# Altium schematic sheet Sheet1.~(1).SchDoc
size A4
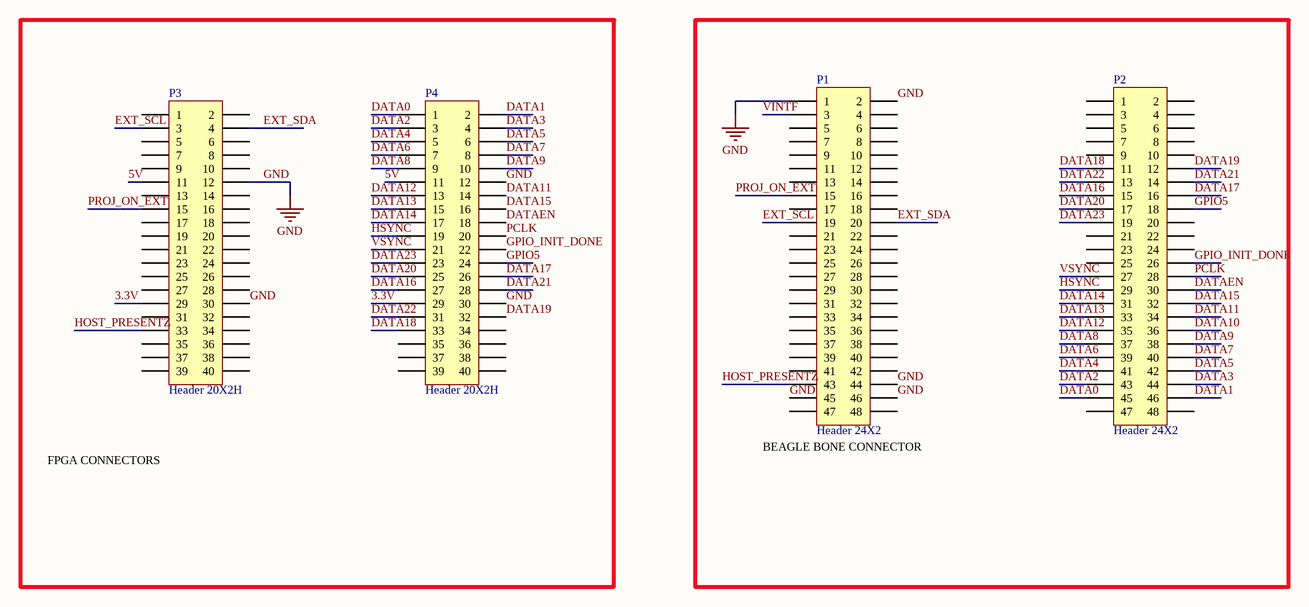
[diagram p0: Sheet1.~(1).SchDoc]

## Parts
P1  Header 24X2  [HDR2X24]
P2  Header 24X2  [HDR2X24]
P3  Header 20X2H  [HDR2X20H]
P4  Header 20X2H  [HDR2X20H]

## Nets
GND: P1.1 P1.2 P1.44 P1.45 P1.46 P3.12 P3.30 P4.12 P4.30
3.3V: P3.29 P4.29
5V: P3.11 P4.11
DATA0: P2.45 P4.1
DATA1: P2.46 P4.2
DATA2: P2.43 P4.3
DATA3: P2.44 P4.4
DATA4: P2.41 P4.5
DATA5: P2.42 P4.6
DATA6: P2.39 P4.7
DATA7: P2.40 P4.8
DATA8: P2.37 P4.9
DATA9: P2.38 P4.10
DATA10: P2.36
DATA11: P2.34 P4.14
DATA12: P2.35 P4.13
DATA13: P2.33 P4.15
DATA14: P2.31 P4.17
DATA15: P2.32 P4.16
DATA16: P2.15 P4.27
DATA17: P2.16 P4.26
DATA18: P2.11 P4.33
DATA19: P2.12 P4.32
DATA20: P2.17 P4.25
DATA21: P2.14 P4.28
DATA22: P2.13 P4.31
DATA23: P2.19 P4.23
DATAEN: P2.30 P4.18
EXT_SCL: P1.19 P3.3
EXT_SDA: P1.20 P3.4
GPIO5: P2.18 P4.24
GPIO_INIT_DONE: P2.26 P4.22
HOST_PRESENTZ: P1.43 P3.33
HSYNC: P2.29 P4.19
PCLK: P2.28 P4.20
PROJ_ON_EXT: P1.15 P3.15
VINTF: P1.3
VSYNC: P2.27 P4.21

Not connected (* = marked no-connect by the designer): P1 4 5 6 7 8 9 10 11 12 13 14 16 17 18 21 22 23 24 25 26 27 28 29 30 31 32 33 34 35 36 37 38 39 40 41 42 47 48; P2 1 2 3 4 5 6 7 8 9 10 20 21 22 23 24 25 47 48; P3 1 2 5 6 7 8 9 10 13 14 16 17 18 19 20 21 22 23 24 25 26 27 28 31 32 34 35 36 37 38 39 40; P4 34 35 36 37 38 39 40

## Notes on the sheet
- FPGA CONNECTORS
- BEAGLE BONE CONNECTOR

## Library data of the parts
P1 P2 = Header 24X2: Header, 24-Pin, Dual row
P3 P4 = Header 20X2H: Header, 20-Pin, Dual row, Right Angle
